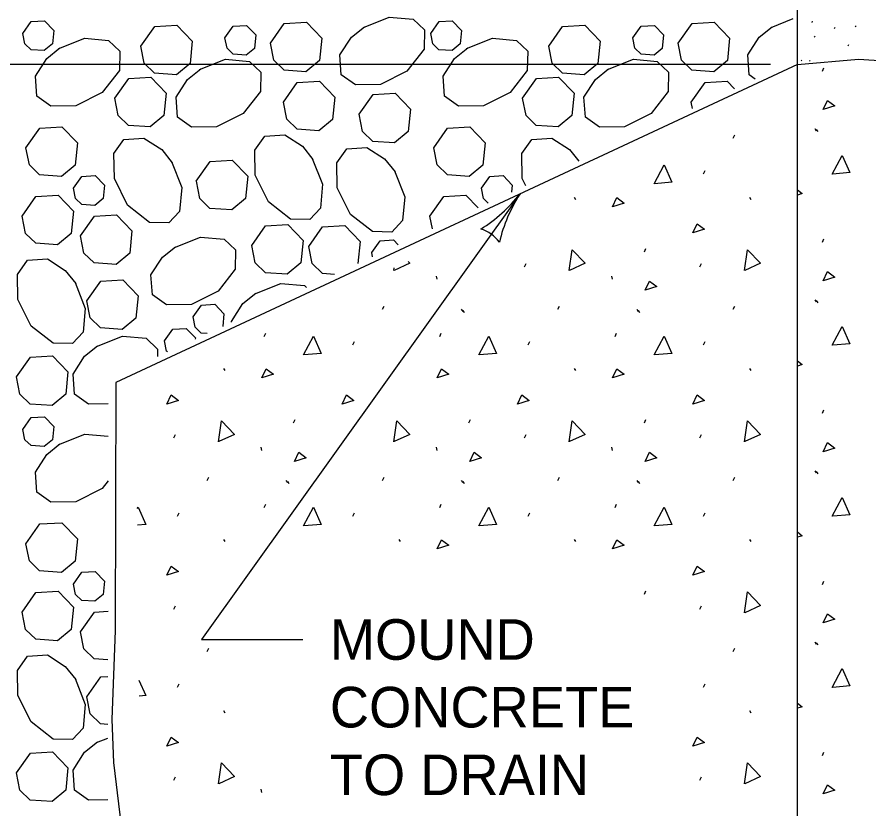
# Model space of a CAD drawing. Extents: x 49991.4 to 50021, y 49987.6 to 50011.4.
# Drawn here: x 50001.858 to 50003.118, y 49993.449 to 49994.619 of the extents above; entities that cross this region are included whole.
import ezdxf

# ---------------------------------------------------------------- set-up
doc = ezdxf.new("R2010")
doc.units = 0
for name, color, linetype in [('Level 1', 7, 'Continuous'), ('Level 2', 7, 'Continuous'), ('Level 3', 7, 'Continuous')]:
    doc.layers.add(name, color=color, linetype=linetype)

msp = doc.modelspace()

# ---------------------------------------------------------------- linework, layer by layer
at = {"layer": 'Level 1'}
for p, q in [((50003.0123, 49990.7229), (50003.0123, 49996.1466)), ((50003.0339, 49994.6108), (50003.0348, 49994.6128)), ((50003.0673, 49994.6018), (50003.0681, 49994.6038)), ((50003.0977, 49994.6061), (50003.0986, 49994.6047)), ((50003.0371, 49994.5905), (50003.038, 49994.5892)), ((50003.0872, 49994.5764), (50003.0881, 49994.5784)), ((50003.0123, 49994.549), (50002.0044, 49994.079)), ((50003.0177, 49994.5554), (50003.0186, 49994.5541)), ((50003.0302, 49994.5549), (50003.0311, 49994.5536)), ((50003.0493, 49994.539), (50003.0515, 49994.5439)), ((50002.9175, 49994.4398), (50002.9197, 49994.4447)), ((50003.0379, 49994.454), (50003.0401, 49994.4508)), ((50003.0401, 49994.4528), (50003.0423, 49994.4496)), ((50002.8736, 49994.3873), (50002.8758, 49994.3921)), ((50002.682, 49994.3526), (50002.6842, 49994.3494)), ((50002.9413, 49994.3526), (50002.9435, 49994.3494)), ((50003.0493, 49994.2862), (50003.0515, 49994.291)), ((50002.786, 49994.272), (50002.7881, 49994.2768)), ((50002.6089, 49994.2498), (50002.6111, 49994.2546)), ((50002.8682, 49994.2498), (50002.8704, 49994.2546)), ((50002.4783, 49994.2362), (50002.4789, 49994.2313)), ((50002.7376, 49994.2362), (50002.7382, 49994.2313)), ((50002.3989, 49994.187), (50002.401, 49994.1918)), ((50002.6582, 49994.187), (50002.6604, 49994.1918)), ((50002.9175, 49994.187), (50002.9197, 49994.1918)), ((50003.0379, 49994.2012), (50003.0401, 49994.1979)), ((50003.0401, 49994.1999), (50003.0423, 49994.1967)), ((50002.5153, 49994.187), (50002.5174, 49994.1837)), ((50002.5174, 49994.1857), (50002.5196, 49994.1825)), ((50002.7746, 49994.187), (50002.7767, 49994.1837)), ((50002.7767, 49994.1857), (50002.7789, 49994.1825)), ((50002.224, 49994.1468), (50002.2262, 49994.1517)), ((50002.4833, 49994.1468), (50002.4855, 49994.1517)), ((50002.7426, 49994.1468), (50002.7448, 49994.1517)), ((50002.355, 49994.1344), (50002.3572, 49994.1393)), ((50002.6143, 49994.1344), (50002.6165, 49994.1393)), ((50002.8736, 49994.1344), (50002.8758, 49994.1393)), ((50002.1634, 49994.0997), (50002.1655, 49994.0965)), ((50002.682, 49994.0997), (50002.6842, 49994.0965)), ((50002.9413, 49994.0997), (50002.9435, 49994.0965)), ((50003.0493, 49994.0333), (50003.0515, 49994.0382)), ((50002.2673, 49994.0191), (50002.2695, 49994.024)), ((50002.5266, 49994.0191), (50002.5288, 49994.024)), ((50002.786, 49994.0191), (50002.7881, 49994.024)), ((50002.0903, 49993.9969), (50002.0925, 49994.0018)), ((50002.6089, 49993.9969), (50002.6111, 49994.0018)), ((50002.8682, 49993.9969), (50002.8704, 49994.0018)), ((50002.219, 49993.9833), (50002.2196, 49993.9784)), ((50002.4783, 49993.9833), (50002.4789, 49993.9784)), ((50002.7376, 49993.9833), (50002.7382, 49993.9784)), ((50002.1396, 49993.9341), (50002.1417, 49993.939)), ((50002.3989, 49993.9341), (50002.401, 49993.939)), ((50002.6582, 49993.9341), (50002.6604, 49993.939)), ((50002.9175, 49993.9341), (50002.9197, 49993.939)), ((50003.0379, 49993.9483), (50003.0401, 49993.9451)), ((50003.0401, 49993.9471), (50003.0423, 49993.9438)), ((50002.256, 49993.9341), (50002.2581, 49993.9308)), ((50002.2581, 49993.9329), (50002.2603, 49993.9296)), ((50002.5153, 49993.9341), (50002.5174, 49993.9308)), ((50002.5174, 49993.9329), (50002.5196, 49993.9296)), ((50002.7746, 49993.9341), (50002.7767, 49993.9308)), ((50002.7767, 49993.9329), (50002.7789, 49993.9296)), ((50002.224, 49993.894), (50002.2262, 49993.8988)), ((50002.4833, 49993.894), (50002.4855, 49993.8988)), ((50002.7426, 49993.894), (50002.7448, 49993.8988)), ((50002.0957, 49993.8815), (50002.0979, 49993.8864)), ((50002.355, 49993.8815), (50002.3572, 49993.8864)), ((50002.6143, 49993.8815), (50002.6165, 49993.8864)), ((50002.8736, 49993.8815), (50002.8758, 49993.8864)), ((50002.1634, 49993.8469), (50002.1655, 49993.8436)), ((50002.4227, 49993.8469), (50002.4249, 49993.8436)), ((50002.682, 49993.8469), (50002.6842, 49993.8436)), ((50002.9413, 49993.8469), (50002.9435, 49993.8436)), ((50003.0493, 49993.7804), (50003.0515, 49993.7853)), ((50002.786, 49993.7662), (50002.7881, 49993.7711)), ((50002.0903, 49993.744), (50002.0925, 49993.7489)), ((50002.8682, 49993.744), (50002.8704, 49993.7489)), ((50003.0379, 49993.6954), (50003.0401, 49993.6922)), ((50003.0401, 49993.6942), (50003.0423, 49993.691)), ((50002.1396, 49993.6812), (50002.1417, 49993.6861)), ((50002.9175, 49993.6812), (50002.9197, 49993.6861)), ((50002.0957, 49993.6286), (50002.0979, 49993.6335)), ((50002.8736, 49993.6286), (50002.8758, 49993.6335)), ((50002.1634, 49993.594), (50002.1655, 49993.5908)), ((50002.9413, 49993.594), (50002.9435, 49993.5908)), ((50003.0493, 49993.5276), (50003.0515, 49993.5324)), ((50002.0903, 49993.4911), (50002.0925, 49993.496)), ((50002.8682, 49993.4911), (50002.8704, 49993.496)), ((50002.219, 49993.4776), (50002.2196, 49993.4727))]:
    msp.add_line(p, q, dxfattribs=at)
for points in [[(50002.3705, 49994.6037), (50002.4088, 49994.6189), (50002.444, 49994.6159), (50002.4607, 49994.6), (50002.4602, 49994.5714), (50002.4348, 49994.5389), (50002.3956, 49994.5193), (50002.3586, 49994.5187), (50002.3377, 49994.5335), (50002.3358, 49994.5629), (50002.3527, 49994.5893), (50002.372, 49994.6047)], [(50001.867, 49994.5947), (50001.8793, 49994.6122), (50001.8989, 49994.6133), (50001.9125, 49994.5992), (50001.9106, 49994.5793), (50001.8984, 49994.5693), (50001.8791, 49994.5707), (50001.8699, 49994.5795), (50001.867, 49994.5947)], [(50002.0415, 49994.576), (50002.062, 49994.6051), (50002.0947, 49994.607), (50002.1174, 49994.5834), (50002.1141, 49994.5504), (50002.0939, 49994.5336), (50002.0616, 49994.5359), (50002.0464, 49994.5507), (50002.0415, 49994.576)], [(50002.1658, 49994.588), (50002.1781, 49994.6055), (50002.1977, 49994.6066), (50002.2114, 49994.5924), (50002.2094, 49994.5726), (50002.1973, 49994.5625), (50002.1779, 49994.5639), (50002.1688, 49994.5728), (50002.1658, 49994.588)], [(50002.233, 49994.5804), (50002.2534, 49994.6096), (50002.2862, 49994.6114), (50002.3089, 49994.5879), (50002.3056, 49994.5548), (50002.2854, 49994.538), (50002.2531, 49994.5403), (50002.2379, 49994.5551), (50002.233, 49994.5804)], [(50002.4701, 49994.5947), (50002.4824, 49994.6122), (50002.502, 49994.6133), (50002.5157, 49994.5992), (50002.5137, 49994.5793), (50002.5016, 49994.5693), (50002.4822, 49994.5707), (50002.4731, 49994.5795), (50002.4701, 49994.5947)], [(50002.6446, 49994.576), (50002.6651, 49994.6051), (50002.6978, 49994.607), (50002.7205, 49994.5834), (50002.7172, 49994.5504), (50002.697, 49994.5336), (50002.6647, 49994.5359), (50002.6495, 49994.5507), (50002.6446, 49994.576)], [(50002.7689, 49994.588), (50002.7812, 49994.6055), (50002.8008, 49994.6066), (50002.8145, 49994.5924), (50002.8125, 49994.5726), (50002.8004, 49994.5625), (50002.781, 49994.5639), (50002.7719, 49994.5728), (50002.7689, 49994.588)], [(50002.8361, 49994.5804), (50002.8566, 49994.6096), (50002.8893, 49994.6114), (50002.912, 49994.5879), (50002.9087, 49994.5548), (50002.8885, 49994.538), (50002.8562, 49994.5403), (50002.841, 49994.5551), (50002.8361, 49994.5804)], [(50002.9736, 49994.6037), (50003.006, 49994.6166)], [(50002.9499, 49994.527), (50002.9408, 49994.5335), (50002.9389, 49994.5629), (50002.9558, 49994.5893), (50002.9751, 49994.6047)], [(50001.9201, 49994.5723), (50001.9584, 49994.5875), (50001.9936, 49994.5844), (50002.0104, 49994.5685), (50002.0098, 49994.5399), (50001.9844, 49994.5075), (50001.9452, 49994.4878), (50001.9082, 49994.4872), (50001.8874, 49994.502), (50001.8854, 49994.5314), (50001.9023, 49994.5578), (50001.9216, 49994.5733)], [(50002.5232, 49994.5723), (50002.5615, 49994.5875), (50002.5967, 49994.5844), (50002.6135, 49994.5685), (50002.6129, 49994.5399), (50002.5875, 49994.5075), (50002.5483, 49994.4878), (50002.5113, 49994.4872), (50002.4905, 49994.502), (50002.4885, 49994.5314), (50002.5054, 49994.5578), (50002.5247, 49994.5733)], [(50002.1283, 49994.5413), (50002.1667, 49994.5565), (50002.2019, 49994.5534), (50002.2186, 49994.5375), (50002.2181, 49994.5089), (50002.1927, 49994.4765), (50002.1534, 49994.4568), (50002.1164, 49994.4562), (50002.0956, 49994.471), (50002.0936, 49994.5005), (50002.1105, 49994.5268), (50002.1299, 49994.5423)], [(50002.7314, 49994.5413), (50002.7698, 49994.5565), (50002.805, 49994.5534), (50002.8217, 49994.5375), (50002.8212, 49994.5089), (50002.7958, 49994.4765), (50002.7565, 49994.4568), (50002.7195, 49994.4562), (50002.6987, 49994.471), (50002.6967, 49994.5005), (50002.7136, 49994.5268), (50002.733, 49994.5423)], [(50003.0123, 49994.549), (50003.1027, 49994.5565), (50003.1644, 49994.5526), (50003.226, 49994.5513), (50003.2548, 49994.5565), (50003.3322, 49994.5565), (50003.403, 49994.5618), (50003.4515, 49994.5513), (50003.5315, 49994.5447), (50003.5709, 49994.5513), (50003.5903, 49994.549)], [(50002.0029, 49994.4989), (50002.0234, 49994.528), (50002.0561, 49994.5299), (50002.0789, 49994.5063), (50002.0756, 49994.4733), (50002.0554, 49994.4565), (50002.0231, 49994.4588), (50002.0079, 49994.4736), (50002.0029, 49994.4989)], [(50002.2522, 49994.4932), (50002.2727, 49994.5223), (50002.3054, 49994.5242), (50002.3282, 49994.5006), (50002.3249, 49994.4676), (50002.3047, 49994.4508), (50002.2724, 49994.4531), (50002.2572, 49994.4678), (50002.2523, 49994.4932)], [(50002.606, 49994.4989), (50002.6265, 49994.528), (50002.6592, 49994.5299), (50002.682, 49994.5063), (50002.6787, 49994.4733), (50002.6585, 49994.4565), (50002.6262, 49994.4588), (50002.611, 49994.4736), (50002.606, 49994.4989)], [(50002.8554, 49994.4932), (50002.8758, 49994.5223), (50002.9086, 49994.5242), (50002.9194, 49994.5129)], [(50002.3643, 49994.4753), (50002.3848, 49994.5045), (50002.4175, 49994.5063), (50002.4402, 49994.4828), (50002.4369, 49994.4497), (50002.4167, 49994.4329), (50002.3844, 49994.4352), (50002.3692, 49994.45), (50002.3643, 49994.4753)], [(50002.8572, 49994.484), (50002.8554, 49994.4932)], [(50003.0504, 49994.4822), (50003.0569, 49994.4957), (50003.0677, 49994.4876), (50003.0504, 49994.4822)], [(50001.8715, 49994.4257), (50001.892, 49994.4549), (50001.9247, 49994.4568), (50001.9475, 49994.4332), (50001.9442, 49994.4001), (50001.924, 49994.3833), (50001.8917, 49994.3857), (50001.8765, 49994.4004), (50001.8715, 49994.4257)], [(50002.4746, 49994.4257), (50002.4951, 49994.4549), (50002.5278, 49994.4568), (50002.5506, 49994.4332), (50002.5473, 49994.4001), (50002.5271, 49994.3833), (50002.4948, 49994.3857), (50002.4796, 49994.4004), (50002.4746, 49994.4257)], [(50002.2949, 49994.4101), (50002.3101, 49994.3718), (50002.307, 49994.3366), (50002.2911, 49994.3198), (50002.2625, 49994.3204), (50002.2301, 49994.3458), (50002.2105, 49994.385), (50002.2098, 49994.422), (50002.2246, 49994.4429), (50002.2541, 49994.4448), (50002.2804, 49994.4279), (50002.2959, 49994.4086)], [(50002.0866, 49994.4052), (50002.1018, 49994.3668), (50002.0988, 49994.3316), (50002.0829, 49994.3149), (50002.0543, 49994.3154), (50002.0218, 49994.3408), (50002.0022, 49994.3801), (50002.0015, 49994.4171), (50002.0163, 49994.4379), (50002.0458, 49994.4399), (50002.0722, 49994.423), (50002.0876, 49994.4036)], [(50002.6105, 49994.3696), (50002.6053, 49994.3801), (50002.6047, 49994.4171), (50002.6195, 49994.4379), (50002.6489, 49994.4399), (50002.6753, 49994.423), (50002.6889, 49994.4059)], [(50002.4164, 49994.3915), (50002.4316, 49994.3532), (50002.4285, 49994.318), (50002.4126, 49994.3012), (50002.384, 49994.3018), (50002.3516, 49994.3272), (50002.3319, 49994.3664), (50002.3313, 49994.4034), (50002.3461, 49994.4243), (50002.3756, 49994.4262), (50002.4019, 49994.4093), (50002.4174, 49994.39)], [(50002.1234, 49994.3762), (50002.1439, 49994.4053), (50002.1766, 49994.4072), (50002.1994, 49994.3836), (50002.1961, 49994.3506), (50002.1759, 49994.3338), (50002.1436, 49994.3361), (50002.1284, 49994.3508), (50002.1235, 49994.3762)], [(50003.0639, 49994.3869), (50003.0786, 49994.4145), (50003.0899, 49994.389), (50003.0645, 49994.3869)], [(50002.8006, 49994.3726), (50002.8152, 49994.4003), (50002.8266, 49994.3748), (50002.8011, 49994.3726)], [(50001.9419, 49994.366), (50001.9542, 49994.3835), (50001.9739, 49994.3846), (50001.9875, 49994.3705), (50001.9855, 49994.3507), (50001.9734, 49994.3406), (50001.954, 49994.342), (50001.9449, 49994.3508), (50001.9419, 49994.366)], [(50002.545, 49994.366), (50002.5573, 49994.3835), (50002.577, 49994.3846), (50002.5906, 49994.3705), (50002.5896, 49994.3599)], [(50001.8658, 49994.3245), (50001.8863, 49994.3537), (50001.919, 49994.3555), (50001.9417, 49994.332), (50001.9384, 49994.2989), (50001.9182, 49994.2821), (50001.8859, 49994.2845), (50001.8707, 49994.2992), (50001.8658, 49994.3245)], [(50002.4689, 49994.3245), (50002.4894, 49994.3537), (50002.5221, 49994.3555), (50002.54, 49994.3369)], [(50002.5551, 49994.3439), (50002.548, 49994.3508), (50002.5451, 49994.366)], [(50003.0123, 49994.3636), (50003.0195, 49994.3582), (50003.0123, 49994.3559)], [(50002.7388, 49994.3385), (50002.7453, 49994.3521), (50002.7562, 49994.344), (50002.7388, 49994.3385)], [(50001.9524, 49994.2956), (50001.9729, 49994.3247), (50002.0056, 49994.3266), (50002.0283, 49994.303), (50002.025, 49994.27), (50002.0048, 49994.2532), (50001.9725, 49994.2555), (50001.9573, 49994.2702), (50001.9524, 49994.2956)], [(50002.4726, 49994.3057), (50002.4689, 49994.3245)], [(50002.2054, 49994.2811), (50002.2259, 49994.3103), (50002.2586, 49994.3122), (50002.2814, 49994.2886), (50002.2781, 49994.2555), (50002.2579, 49994.2387), (50002.2256, 49994.2411), (50002.2104, 49994.2558), (50002.2055, 49994.2811)], [(50002.2897, 49994.2799), (50002.3102, 49994.3091), (50002.3429, 49994.3109), (50002.3657, 49994.2873), (50002.3624, 49994.2546)], [(50002.8575, 49994.2998), (50002.864, 49994.3134), (50002.8748, 49994.3053), (50002.8575, 49994.2998)], [(50002.0911, 49994.2785), (50002.1295, 49994.2937), (50002.1647, 49994.2906), (50002.1814, 49994.2747), (50002.1809, 49994.2461), (50002.1555, 49994.2137), (50002.1162, 49994.194), (50002.0792, 49994.1934), (50002.0584, 49994.2082), (50002.0564, 49994.2377), (50002.0733, 49994.264), (50002.0927, 49994.2795)], [(50002.3278, 49994.2385), (50002.3099, 49994.2398), (50002.2947, 49994.2546), (50002.2898, 49994.2799)], [(50002.383, 49994.2709), (50002.3953, 49994.2884), (50002.4149, 49994.2895), (50002.422, 49994.2822)], [(50002.3842, 49994.2647), (50002.383, 49994.2709)], [(50002.6748, 49994.2442), (50002.6791, 49994.2751), (50002.6985, 49994.2551), (50002.6753, 49994.2443)], [(50002.9341, 49994.2442), (50002.9384, 49994.2751), (50002.9578, 49994.2551), (50002.9346, 49994.2443)], [(50001.9441, 49994.2267), (50001.9593, 49994.1883), (50001.9562, 49994.1531), (50001.9403, 49994.1364), (50001.9117, 49994.1369), (50001.8793, 49994.1623), (50001.8596, 49994.2016), (50001.859, 49994.2386), (50001.8738, 49994.2594), (50001.9033, 49994.2614), (50001.9296, 49994.2445), (50001.9451, 49994.2251)], [(50002.4366, 49994.2577), (50002.4391, 49994.2551), (50002.416, 49994.2443)], [(50002.4155, 49994.2442), (50002.416, 49994.2482)], [(50003.0504, 49994.2293), (50003.0569, 49994.2429), (50003.0677, 49994.2347), (50003.0504, 49994.2293)], [(50001.9615, 49994.1997), (50001.982, 49994.2288), (50002.0147, 49994.2307), (50002.0374, 49994.2071), (50002.0341, 49994.1741), (50002.0139, 49994.1573), (50001.9816, 49994.1596), (50001.9664, 49994.1743), (50001.9615, 49994.1997)], [(50002.787, 49994.2151), (50002.7935, 49994.2286), (50002.8044, 49994.2205), (50002.787, 49994.2151)], [(50002.2101, 49994.21), (50002.2484, 49994.2252), (50002.2836, 49994.2222), (50002.2865, 49994.2194)], [(50002.1755, 49994.1679), (50002.1754, 49994.1692), (50002.1923, 49994.1955), (50002.2116, 49994.211)], [(50002.1187, 49994.1758), (50002.131, 49994.1933), (50002.1507, 49994.1944), (50002.1643, 49994.1802), (50002.1625, 49994.1618)], [(50002.1393, 49994.1511), (50002.1308, 49994.1517), (50002.1217, 49994.1606), (50002.1187, 49994.1758)], [(50002.0765, 49994.1402), (50002.0888, 49994.1577), (50002.1084, 49994.1588), (50002.122, 49994.1447), (50002.1219, 49994.143)], [(50003.0639, 49994.134), (50003.0786, 49994.1616), (50003.0899, 49994.1362), (50003.0645, 49994.134)], [(50001.9758, 49994.1319), (50002.0142, 49994.1471), (50002.0494, 49994.1441), (50002.0661, 49994.1282), (50002.0659, 49994.117)], [(50002.0806, 49994.1239), (50002.0794, 49994.125), (50002.0765, 49994.1402)], [(50002.2819, 49994.1198), (50002.2966, 49994.1474), (50002.3079, 49994.1219), (50002.2825, 49994.1198)], [(50002.5413, 49994.1198), (50002.5559, 49994.1474), (50002.5672, 49994.1219), (50002.5418, 49994.1198)], [(50002.8006, 49994.1198), (50002.8152, 49994.1474), (50002.8266, 49994.1219), (50002.8011, 49994.1198)], [(50001.9931, 49994.0473), (50001.9639, 49994.0468), (50001.9431, 49994.0616), (50001.9411, 49994.0911), (50001.958, 49994.1175), (50001.9774, 49994.1329)], [(50001.8576, 49994.087), (50001.8781, 49994.1161), (50001.9109, 49994.118), (50001.9336, 49994.0944), (50001.9303, 49994.0614), (50001.9101, 49994.0446), (50001.8778, 49994.0469), (50001.8626, 49994.0616), (50001.8577, 49994.087)], [(50003.0123, 49994.1107), (50003.0195, 49994.1053), (50003.0123, 49994.103)], [(50002.2202, 49994.0857), (50002.2267, 49994.0992), (50002.2375, 49994.0911), (50002.2202, 49994.0857)], [(50002.4795, 49994.0857), (50002.486, 49994.0992), (50002.4969, 49994.0911), (50002.4795, 49994.0857)], [(50002.7388, 49994.0857), (50002.7453, 49994.0992), (50002.7562, 49994.0911), (50002.7388, 49994.0857)], [(50002.0044, 49994.079), (50002.0035, 49993.7124)], [(50002.0796, 49994.047), (50002.0861, 49994.0605), (50002.0969, 49994.0524), (50002.0796, 49994.047)], [(50002.3389, 49994.047), (50002.3454, 49994.0605), (50002.3562, 49994.0524), (50002.3389, 49994.047)], [(50002.5982, 49994.047), (50002.6047, 49994.0605), (50002.6155, 49994.0524), (50002.5982, 49994.047)], [(50002.8575, 49994.047), (50002.864, 49994.0605), (50002.8748, 49994.0524), (50002.8575, 49994.047)], [(50001.867, 49994.0095), (50001.8793, 49994.027), (50001.8989, 49994.0281), (50001.9125, 49994.014), (50001.9106, 49993.9942), (50001.8984, 49993.9841), (50001.8791, 49993.9855), (50001.8699, 49993.9943), (50001.867, 49994.0095)], [(50002.1562, 49993.9913), (50002.1605, 49994.0222), (50002.1798, 49994.0022), (50002.1567, 49993.9915)], [(50002.4155, 49993.9913), (50002.4198, 49994.0222), (50002.4391, 49994.0022), (50002.416, 49993.9915)], [(50002.6748, 49993.9913), (50002.6791, 49994.0222), (50002.6985, 49994.0022), (50002.6753, 49993.9915)], [(50002.9341, 49993.9913), (50002.9384, 49994.0222), (50002.9578, 49994.0022), (50002.9346, 49993.9915)], [(50001.9201, 49993.9871), (50001.9584, 49994.0023), (50001.9931, 49993.9993)], [(50003.0504, 49993.9765), (50003.0569, 49993.99), (50003.0677, 49993.9819), (50003.0504, 49993.9765)], [(50001.993, 49993.9333), (50001.9844, 49993.9223), (50001.9452, 49993.9026), (50001.9082, 49993.902), (50001.8874, 49993.9168), (50001.8854, 49993.9463), (50001.9023, 49993.9726), (50001.9216, 49993.9881)], [(50002.2684, 49993.9622), (50002.2749, 49993.9758), (50002.2857, 49993.9677), (50002.2684, 49993.9622)], [(50002.5277, 49993.9622), (50002.5342, 49993.9758), (50002.545, 49993.9677), (50002.5277, 49993.9622)], [(50002.787, 49993.9622), (50002.7935, 49993.9758), (50002.8044, 49993.9677), (50002.787, 49993.9622)], [(50003.0639, 49993.8811), (50003.0786, 49993.9087), (50003.0899, 49993.8833), (50003.0645, 49993.8811)], [(50002.0362, 49993.8926), (50002.0373, 49993.8945), (50002.0486, 49993.8691), (50002.0364, 49993.868)], [(50002.2819, 49993.8669), (50002.2966, 49993.8945), (50002.3079, 49993.8691), (50002.2825, 49993.8669)], [(50002.5413, 49993.8669), (50002.5559, 49993.8945), (50002.5672, 49993.8691), (50002.5418, 49993.8669)], [(50002.8006, 49993.8669), (50002.8152, 49993.8945), (50002.8266, 49993.8691), (50002.8011, 49993.8669)], [(50001.8715, 49993.8406), (50001.892, 49993.8697), (50001.9247, 49993.8716), (50001.9475, 49993.848), (50001.9442, 49993.815), (50001.924, 49993.7981), (50001.8917, 49993.8005), (50001.8765, 49993.8152), (50001.8715, 49993.8406)], [(50003.0123, 49993.8579), (50003.0195, 49993.8524), (50003.0123, 49993.8502)], [(50002.4795, 49993.8328), (50002.486, 49993.8463), (50002.4969, 49993.8382), (50002.4795, 49993.8328)], [(50002.7388, 49993.8328), (50002.7453, 49993.8463), (50002.7562, 49993.8382), (50002.7388, 49993.8328)], [(50002.0796, 49993.7941), (50002.0861, 49993.8076), (50002.0969, 49993.7995), (50002.0796, 49993.7941)], [(50002.8575, 49993.7941), (50002.864, 49993.8076), (50002.8748, 49993.7995), (50002.8575, 49993.7941)], [(50001.9419, 49993.7808), (50001.9542, 49993.7983), (50001.9739, 49993.7995), (50001.9875, 49993.7853), (50001.9855, 49993.7655), (50001.9734, 49993.7554), (50001.954, 49993.7568), (50001.9449, 49993.7656), (50001.9419, 49993.7808)], [(50001.8658, 49993.7393), (50001.8863, 49993.7685), (50001.919, 49993.7704), (50001.9417, 49993.7468), (50001.9384, 49993.7137), (50001.9182, 49993.6969), (50001.8859, 49993.6993), (50001.8707, 49993.714), (50001.8658, 49993.7393)], [(50002.9341, 49993.7384), (50002.9384, 49993.7694), (50002.9578, 49993.7493), (50002.9346, 49993.7386)], [(50001.9524, 49993.7104), (50001.9729, 49993.7395), (50001.9929, 49993.7407)], [(50003.0504, 49993.7236), (50003.0569, 49993.7371), (50003.0677, 49993.729), (50003.0504, 49993.7236)], [(50002.0035, 49993.7124), (50001.9984, 49993.5807), (50002.0012, 49993.5173), (50002.0103, 49993.4399), (50002.0092, 49993.3664), (50002.0108, 49993.3438), (50002.008, 49993.3003), (50002.012, 49993.2482), (50002.0092, 49993.2081), (50002.0114, 49993.1894), (50002.0052, 49993.1052), (50002.0012, 49993.047), (50002.0041, 49993.0317), (50002.0018, 49993.0012)], [(50001.9928, 49993.6689), (50001.9725, 49993.6703), (50001.9573, 49993.6851), (50001.9524, 49993.7104)], [(50001.9441, 49993.6415), (50001.9593, 49993.6031), (50001.9562, 49993.5679), (50001.9403, 49993.5512), (50001.9117, 49993.5517), (50001.8793, 49993.5771), (50001.8596, 49993.6164), (50001.859, 49993.6534), (50001.8738, 49993.6742), (50001.9033, 49993.6762), (50001.9296, 49993.6593), (50001.9451, 49993.6399)], [(50003.0639, 49993.6282), (50003.0786, 49993.6559), (50003.0899, 49993.6304), (50003.0645, 49993.6282)], [(50001.9615, 49993.6145), (50001.982, 49993.6437), (50001.9928, 49993.6443)], [(50002.0385, 49993.6388), (50002.0486, 49993.6162), (50002.0387, 49993.6154)], [(50001.9927, 49993.5736), (50001.9816, 49993.5744), (50001.9664, 49993.5892), (50001.9615, 49993.6145)], [(50003.0123, 49993.605), (50003.0195, 49993.5996), (50003.0123, 49993.5973)], [(50001.9758, 49993.5467), (50001.9927, 49993.5534)], [(50002.0796, 49993.5412), (50002.0861, 49993.5548), (50002.0969, 49993.5466), (50002.0796, 49993.5412)], [(50002.8575, 49993.5412), (50002.864, 49993.5548), (50002.8748, 49993.5466), (50002.8575, 49993.5412)], [(50001.9926, 49993.4622), (50001.9639, 49993.4616), (50001.9431, 49993.4764), (50001.9411, 49993.5059), (50001.958, 49993.5323), (50001.9774, 49993.5477)], [(50001.8576, 49993.5018), (50001.8781, 49993.5309), (50001.9109, 49993.5328), (50001.9336, 49993.5092), (50001.9303, 49993.4762), (50001.9101, 49993.4594), (50001.8778, 49993.4617), (50001.8626, 49993.4764), (50001.8577, 49993.5018)], [(50002.1562, 49993.4855), (50002.1605, 49993.5165), (50002.1798, 49993.4965), (50002.1567, 49993.4857)], [(50002.9341, 49993.4855), (50002.9384, 49993.5165), (50002.9578, 49993.4965), (50002.9346, 49993.4857)], [(50003.0504, 49993.4707), (50003.0569, 49993.4843), (50003.0677, 49993.4761), (50003.0504, 49993.4707)]]:
    msp.add_lwpolyline(points, dxfattribs=at)
at = {"layer": 'Level 3'}
for p, q in [((50002.9723, 49994.549), (50000.9473, 49994.549)), ((50002.6022, 49994.3578), (50002.1309, 49993.699)), ((50002.1309, 49993.699), (50002.2809, 49993.699))]:
    msp.add_line(p, q, dxfattribs=at)
for centre, radius, start, end in [((50002.4268, 49994.4944), 0.2223, 301.875, 322.0585), ((50002.7981, 49994.2317), 0.233, 147.2463, 166.4962), ((50002.5276, 49994.2535), 0.0548, 36.5578, 72.2802)]:
    msp.add_arc(centre, radius, start, end, dxfattribs=at)

# ---------------------------------------------------------------- texts
at = {"layer": 'Level 2'}
for s, p in [('MOUND', (50002.3209, 49993.669)), ('CONCRETE', (50002.3209, 49993.569)), ('TO DRAIN', (50002.3209, 49993.469))]:
    msp.add_text(s, height=0.06, dxfattribs=at).set_placement(p)

doc.saveas('drawing.dxf')
